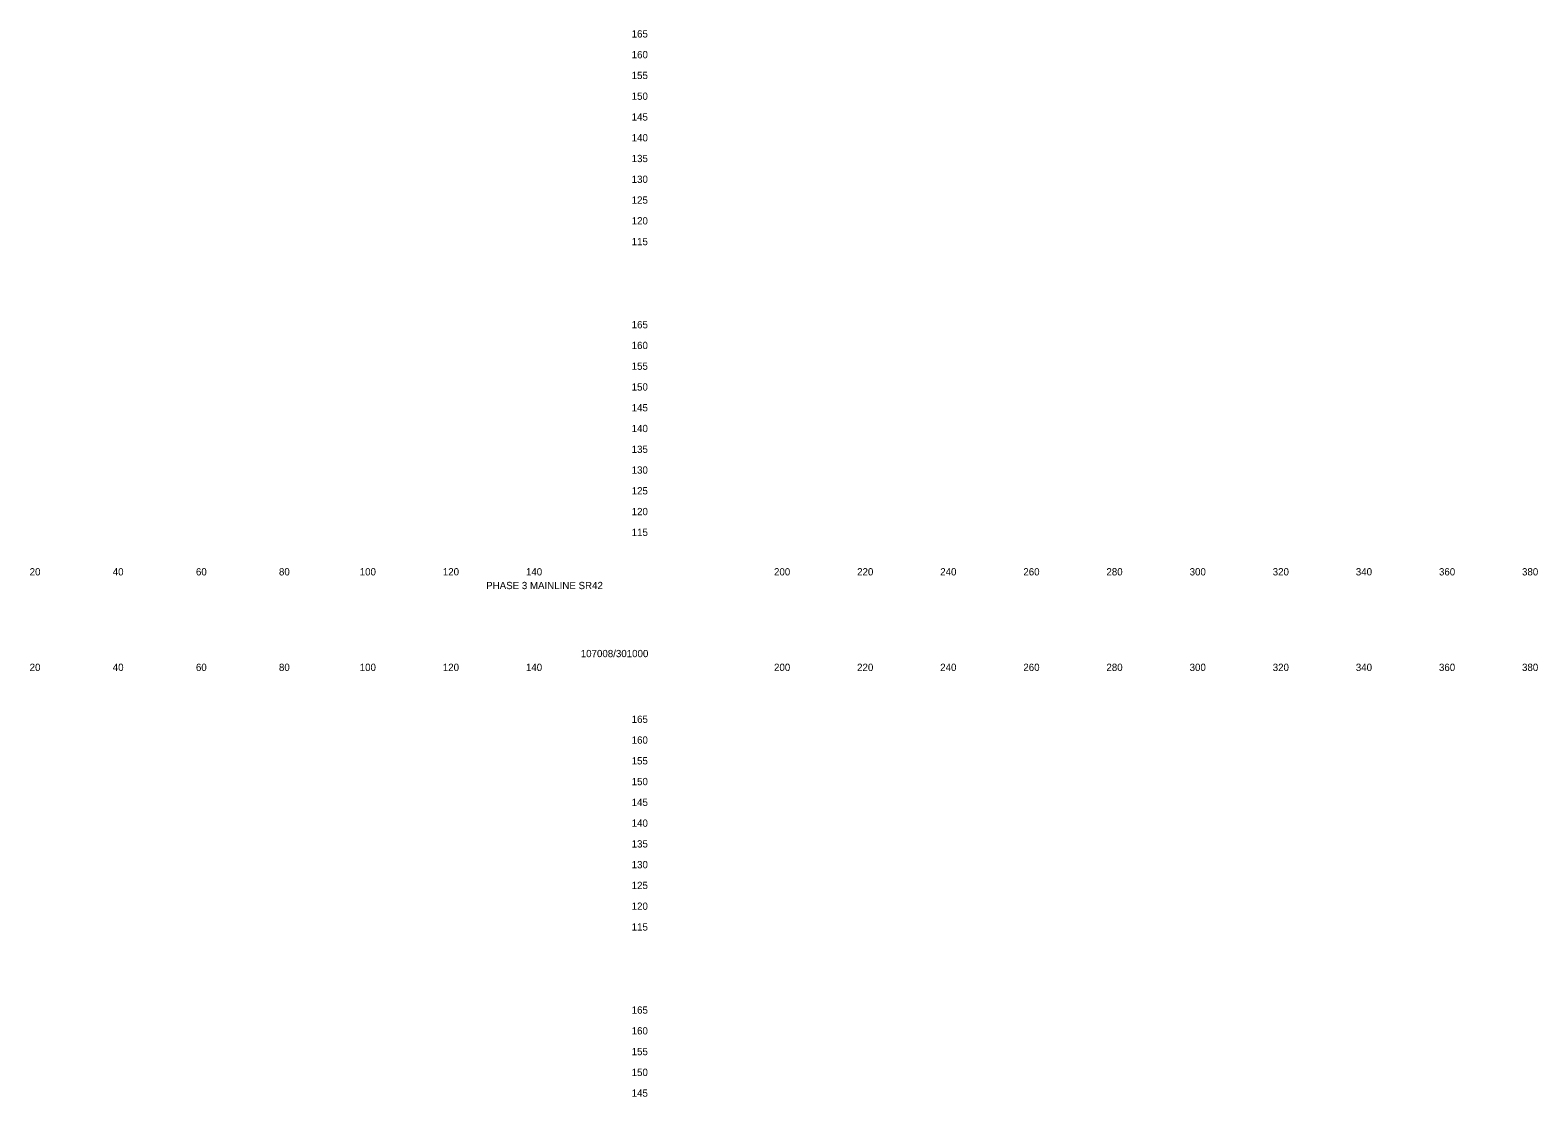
# Model space of a CAD drawing. Extents: x 21281 to 22024, y 6472 to 15198.
# Drawn here: x 21661.4 to 22024.2, y 8649.8 to 8906.6 of the extents above; entities that cross this region are included whole.
import ezdxf

# ---------------------------------------------------------------- set-up
doc = ezdxf.new("R2010")
doc.units = 0
doc.layers.add('Draft_XS_Grid', color=7, linetype='Continuous')
doc.layers.add('Draft_XS_Text', color=7, linetype='Continuous')

msp = doc.modelspace()

# ---------------------------------------------------------------- texts
at = {"layer": 'Draft_XS_Grid'}
for s, p in [('  165  ', (21804.84, 8904.84)), ('  160  ', (21804.84, 8899.84)), ('  155  ', (21804.84, 8894.84)), ('  150  ', (21804.84, 8889.84)), ('  145  ', (21804.84, 8884.84)), ('  140  ', (21804.84, 8879.84)), ('  135  ', (21804.84, 8874.84)), ('  130  ', (21804.84, 8869.84)), ('  125  ', (21804.84, 8864.84)), ('  120  ', (21804.84, 8859.84)), ('  115  ', (21804.84, 8854.84)), ('  165  ', (21804.84, 8834.84)), ('  160  ', (21804.84, 8829.84)), ('  155  ', (21804.84, 8824.84)), ('  150  ', (21804.84, 8819.84)), ('  145  ', (21804.84, 8814.84)), ('  140  ', (21804.84, 8809.84)), ('  135  ', (21804.84, 8804.84)), ('  130  ', (21804.84, 8799.84)), ('  125  ', (21804.84, 8794.84)), ('  120  ', (21804.84, 8789.84)), ('  115  ', (21804.84, 8784.84)), ('  165  ', (21804.84, 8739.84)), ('  160  ', (21804.84, 8734.84)), ('  155  ', (21804.84, 8729.84)), ('  150  ', (21804.84, 8724.84)), ('  145  ', (21804.84, 8719.84)), ('  140  ', (21804.84, 8714.84)), ('  135  ', (21804.84, 8709.84)), ('  130  ', (21804.84, 8704.84)), ('  125  ', (21804.84, 8699.84)), ('  120  ', (21804.84, 8694.84)), ('  115  ', (21804.84, 8689.84)), ('  165  ', (21804.84, 8669.84)), ('  160  ', (21804.84, 8664.84)), ('  155  ', (21804.84, 8659.84)), ('  150  ', (21804.84, 8654.84)), ('  145  ', (21804.84, 8649.84))]:
    msp.add_text(s, height=1.75, dxfattribs=at).set_placement(p)
at = {"layer": 'Draft_XS_Text'}
for s, p in [('  20  ', (21659.95, 8775.34)), ('  40  ', (21679.95, 8775.34)), ('  60  ', (21699.97, 8775.34)), ('  80  ', (21719.95, 8775.34)), ('  100  ', (21739.39, 8775.34)), ('  120  ', (21759.39, 8775.34)), ('  140  ', (21779.39, 8775.34)), ('  200  ', (21839.1, 8775.34)), ('  220  ', (21859.1, 8775.34)), ('  240  ', (21879.1, 8775.34)), ('  260  ', (21899.11, 8775.34)), ('  280  ', (21919.1, 8775.34)), ('  300  ', (21939.13, 8775.34)), ('  320  ', (21959.13, 8775.34)), ('  340  ', (21979.13, 8775.34)), ('  360  ', (21999.14, 8775.34)), ('  380  ', (22019.13, 8775.34)), ('PHASE 3 MAINLINE SR42', (21771.12, 8772.04)), ('107008/301000', (21793.89, 8755.66)), ('  20  ', (21659.95, 8752.34)), ('  40  ', (21679.95, 8752.34)), ('  60  ', (21699.97, 8752.34)), ('  80  ', (21719.95, 8752.34)), ('  100  ', (21739.39, 8752.34)), ('  120  ', (21759.39, 8752.34)), ('  140  ', (21779.39, 8752.34)), ('  200  ', (21839.1, 8752.34)), ('  220  ', (21859.1, 8752.34)), ('  240  ', (21879.1, 8752.34)), ('  260  ', (21899.11, 8752.34)), ('  280  ', (21919.1, 8752.34)), ('  300  ', (21939.13, 8752.34)), ('  320  ', (21959.13, 8752.34)), ('  340  ', (21979.13, 8752.34)), ('  360  ', (21999.14, 8752.34)), ('  380  ', (22019.13, 8752.34))]:
    msp.add_text(s, height=1.75, dxfattribs=at).set_placement(p)

doc.saveas('drawing.dxf')
